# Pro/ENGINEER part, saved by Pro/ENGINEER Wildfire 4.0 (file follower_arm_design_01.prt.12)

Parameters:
  METRIC = "NO"

Other parameters: PITCH, DRILL_DIAMETER, THREAD_DIAMETER, THREADS_PER_INCH, THREAD_DEPTH, THREAD_LENGTH, DRILL_POINT_ANGLE, DRILL_DEPTH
